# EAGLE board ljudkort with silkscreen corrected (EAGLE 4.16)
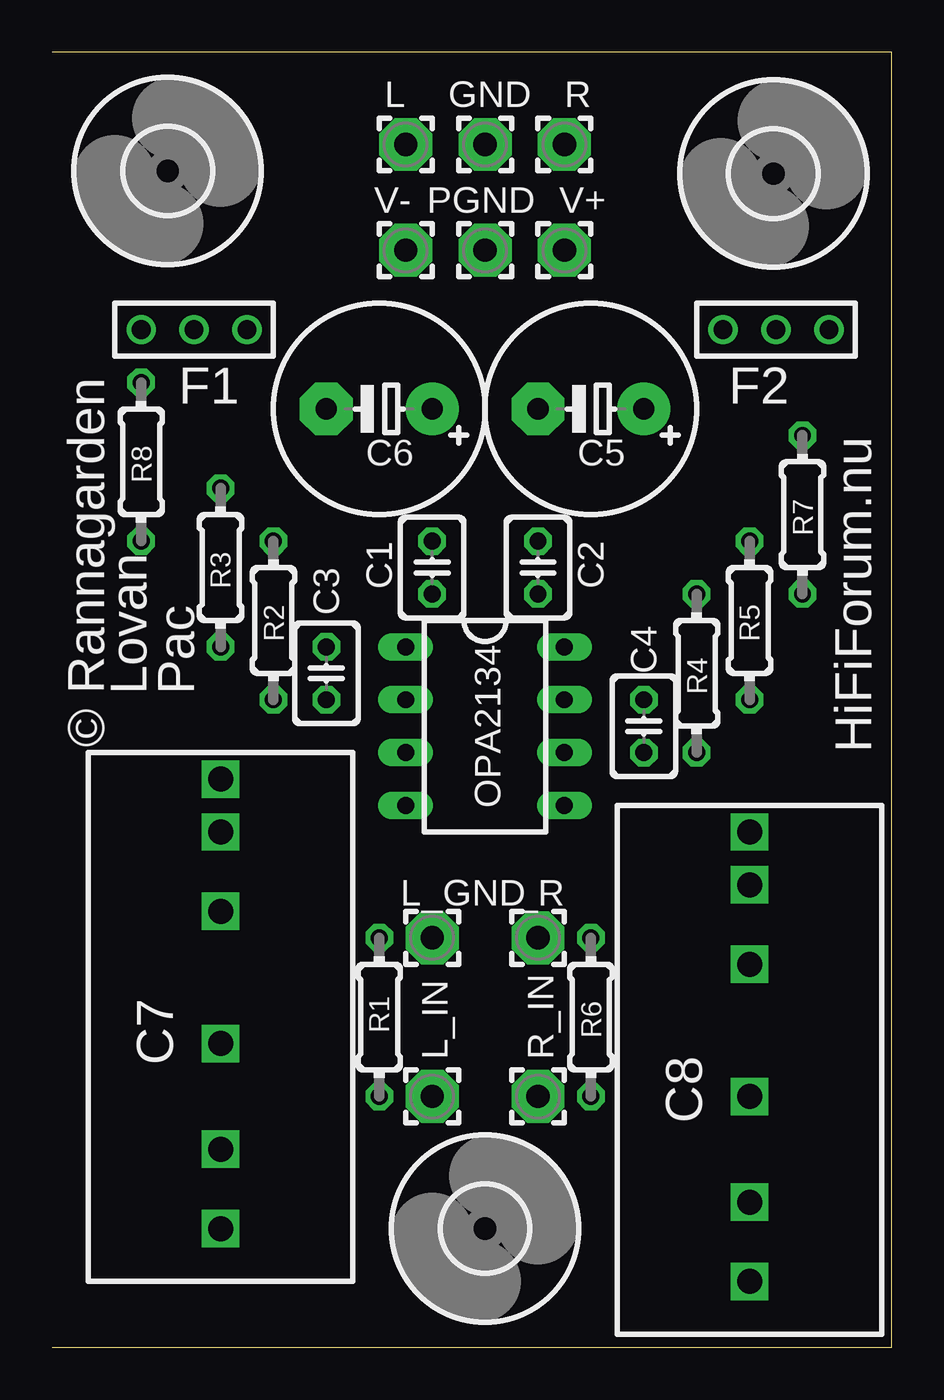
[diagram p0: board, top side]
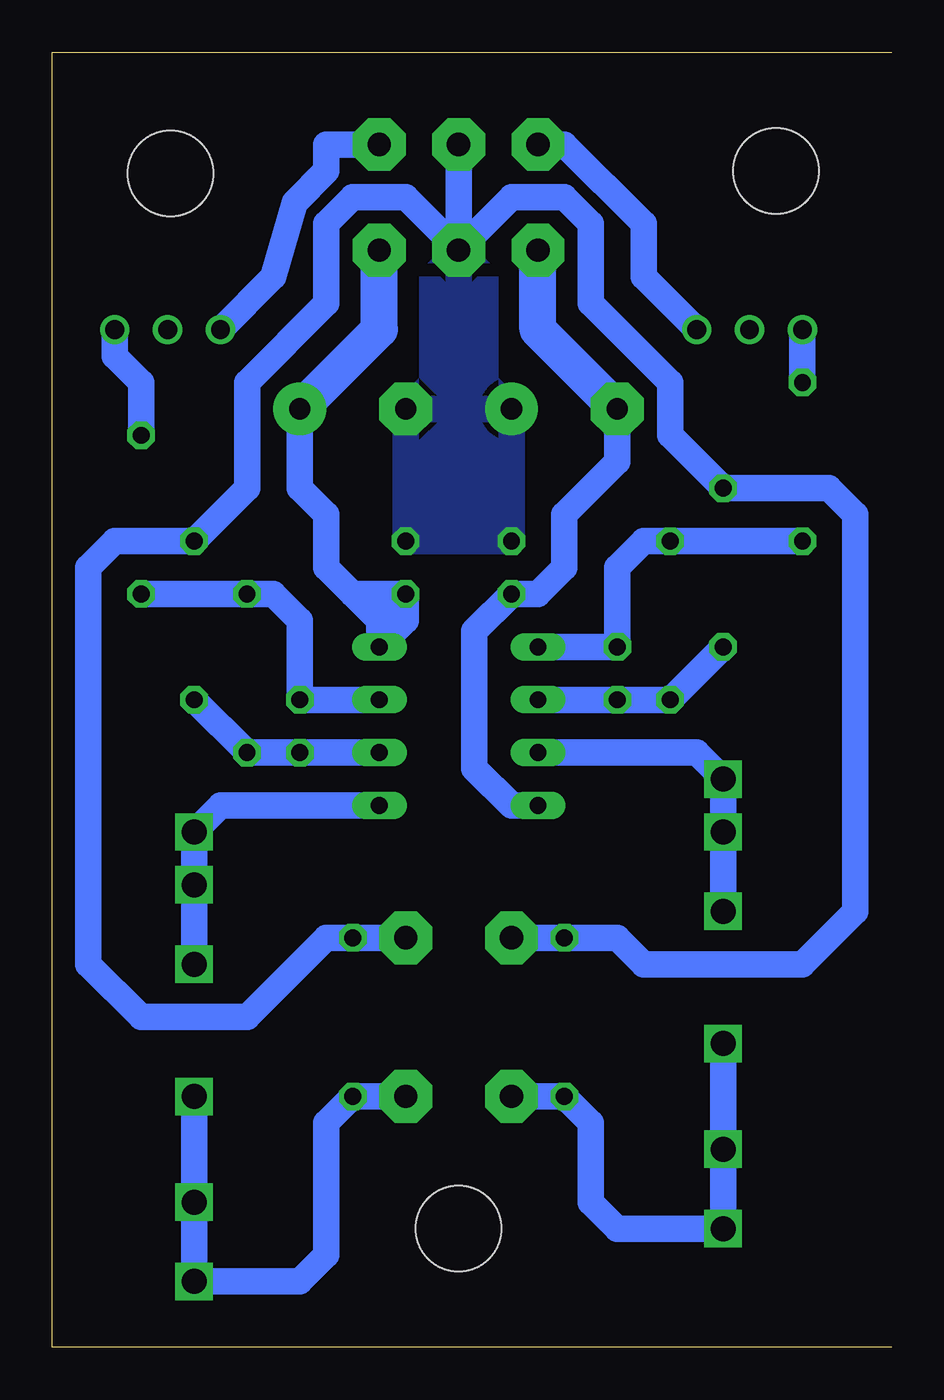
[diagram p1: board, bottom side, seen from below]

Size 40.31 x 62.22 mm. Coordinates in mm from the lower left corner, seen from the top.
Outline: 0,0 40.31,0 40.31,62.22 0,62.22
Copper layers (1*16): Top 0.035mm / dielectric 1.5mm / Bottom 0.035mm
Design rules "10mils": minimum track width 10mil, minimum drill 24mil, track to track 10mil, track to pad 10mil, pad to pad 10mil, via to via 10mil, smd to smd 10mil, copper to edge 40mil, drill to drill 10mil, minimum pad ring 10mil, minimum via ring 8mil, stop-mask expansion 0mil, vias tented up to drill 0mil, thermal gap 10mil

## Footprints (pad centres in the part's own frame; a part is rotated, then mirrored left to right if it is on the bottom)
2,54/1,1 = drill 1.118 pad 2.54 octagon: 1 0,0
C025-030X050 = drill 0.813 octagon: 1 -1.27,0; 2 1.27,0
E5-10,5 = drill 1.016 pad 2.54 round: + -2.54,0 | drill 1.016 pad 2.54 octagon: - 2.54,0
DIL08 = drill 0.813 long: 1 -3.81,-3.81; 2 -1.27,-3.81; 3 1.27,-3.81; 4 3.81,-3.81; 5 3.81,3.81; 6 1.27,3.81; 7 -1.27,3.81; 8 -3.81,3.81
0204/7 = drill 0.813 octagon: 1 -3.81,0; 2 3.81,0
3STIFT = drill 0.9 round: P$1 1.27,1.27; P$2 3.81,1.27; P$3 6.35,1.27
4,1 = hole 4.1: 0,0
KONDING = drill 1.2 square: P$1 0,-11.43; P$2 0,6.35; P$3 0,-8.89; P$4 0,1.27; P$5 0,10.16; P$9 0,-5.08

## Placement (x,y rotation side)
_R  [2,54/1,1]  23.33,19.68 0 top
C1  0,1uf  [C025-030X050]  18.25,37.46 270 top
C2  0,1uf  [C025-030X050]  23.33,37.46 90 top
C3  0,1uf  [C025-030X050]  13.17,32.38 90 top
C4  0,1uf  [C025-030X050]  28.41,29.84 90 top
C5  [E5-10,5]  25.87,45.08 180 top
C6  [E5-10,5]  15.71,45.08 180 top
GND  [2,54/1,1]  20.79,57.78 0 top
L  [2,54/1,1]  16.98,57.78 0 top
L_GND  [2,54/1,1]  18.25,19.68 0 top
L_IN  [2,54/1,1]  18.25,12.06 0 top
OPA2134  OPA2134  [DIL08]  20.79,29.84 270 top
PGND  [2,54/1,1]  20.79,52.7 0 top
R  [2,54/1,1]  24.6,57.78 0 top
R1  200k  [0204/7]  15.71,15.87 90 top
R2  47k  [0204/7]  10.63,34.92 270 top
R3  12k  [0204/7]  8.09,37.46 90 top
R4  47k  [0204/7]  30.95,32.38 270 top
R5  12k  [0204/7]  33.49,34.92 90 top
R6  200k  [0204/7]  25.87,15.87 270 top
R7  0R  [0204/7]  36.03,40 270 top
R8  0R  [0204/7]  4.28,42.54 270 top
R_IN  [2,54/1,1]  23.33,12.06 0 top
U$2  3PINSTIFT  [3STIFT]  3.01,47.62 0 top
U$3  3PINSTIFT  [3STIFT]  38.57,50.16 180 top
U$4  [4,1]  20.79,5.71 0 top
U$5  [4,1]  5.55,56.51 0 top
U$6  [4,1]  34.63,56.38 0 top
U$7  INKONDING  [KONDING]  8.09,15.87 180 top
U$8  INKONDING  [KONDING]  33.49,13.33 180 top
V+  [2,54/1,1]  24.6,52.7 0 top
V-  [2,54/1,1]  16.98,52.7 0 top

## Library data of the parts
_R GND L L_GND L_IN PGND R R_IN V+ V- = wirepad
C1-C6 R1-R8 = rcl
OPA2134 U$2 U$3 U$7 U$8 = Rannagarden
U$4-U$6 = holes

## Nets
GND: _R.1 C1.1 C2.2 C5.- C6.+ GND.1 L_GND.1 PGND.1 R1.2 R3.2 R5.2 R6.1
N$1: L_IN.1 R1.1 U$7.P$2 U$7.P$4 U$7.P$5
N$3: C3.1 OPA2134.2 R2.2 R3.1
N$4: C4.1 OPA2134.6 R4.2 R5.1
N$5: C3.2 OPA2134.1 R2.1 R8.2
N$6: C1.2 C6.- OPA2134.4 V-.1
N$7: C2.1 C5.+ OPA2134.8 V+.1
N$8: C4.2 OPA2134.7 R4.1 R7.2
N$9: R6.2 R_IN.1 U$8.P$2 U$8.P$4 U$8.P$5
N$10: R8.1 U$2.P$1
N$11: R.1 U$3.P$3
N$12: L.1 U$2.P$3
N$13: R7.1 U$3.P$1
N$15: OPA2134.5 U$8.P$1 U$8.P$3 U$8.P$9
N$18: OPA2134.3 U$7.P$1 U$7.P$3 U$7.P$9

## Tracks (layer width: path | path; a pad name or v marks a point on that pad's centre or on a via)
GND
  Bottom 1.27: L_GND.1 R1.2 13.17,19.68 11.9,18.41 4.28,18.41 1.74,20.95 1.74,40 3.01,41.27 R3.2 10.63,43.81 10.63,46.35 14.44,50.16 14.44,53.97 15.71,55.24 18.25,55.24 PGND.1 | R6.1 _R.1 27.14,19.68 30.95,15.87 36.03,15.87 38.57,18.41 38.57,37.46 37.3,38.73 R5.2 30.95,41.27 30.95,46.35 27.14,50.16 27.14,53.97 25.87,55.24 23.33,55.24 PGND.1 | PGND.1 GND.1
  pour Bottom: 20.79,52.7 19.52,51.43 19.52,46.35 18.25,45.08 18.25,38.73 23.33,38.73 23.33,45.08 22.06,46.35 22.06,51.43
N$1
  Bottom 1.27: L_IN.1 R1.1 14.44,10.79 14.44,6.98 13.17,5.71 U$7.P$5 U$7.P$2 U$7.P$4
N$3
  Bottom 1.27: OPA2134.2 C3.1 R2.2 R3.1
N$4
  Bottom 1.27: R5.1 R4.2 C4.1 OPA2134.6
N$5
  Bottom 1.27: OPA2134.1 C3.2 13.17,37.46 11.9,38.73 R2.1 R8.2
N$6
  Bottom 1.27: OPA2134.4 18.25,26.03 20.03,27.81 20.03,34.41 C1.2 16.98,36.19 15.71,37.46 15.71,40 13.17,42.54 C6.-
  Bottom 1.778: C6.- 16.98,48.89 V-.1
N$7
  Bottom 1.27: C5.+ 28.41,41.27 27.14,40 27.14,37.46 25.87,36.19 | 24.6,36.19 C2.1 23.33,34.92 OPA2134.8 | 24.6,36.19 25.87,36.19 | OPA2134.8 24.6,34.92 25.87,36.19 | OPA2134.8 24.6,36.19
  Bottom 1.778: C5.+ 24.6,48.89 V+.1
N$8
  Bottom 1.27: OPA2134.7 C4.2 28.41,34.92 29.68,36.19 R4.1 R7.2
N$9
  Bottom 1.27: R_IN.1 R6.2 27.14,10.79 27.14,4.44 28.41,3.17 U$8.P$5 U$8.P$2 U$8.P$4
N$10
  Bottom 1.27: R8.1 U$2.P$1
N$11
  Bottom 1.27: U$3.P$3 29.68,51.43 28.66,54.99 27.14,56.51 27.14,57.78 R.1
N$12
  Bottom 1.27: U$2.P$3 11.9,51.43 11.9,53.97 15.71,57.78 L.1
N$13
  Bottom 1.27: R7.1 36.03,46.35 37.3,47.62 U$3.P$1
N$15
  Bottom 1.27: U$8.P$9 U$8.P$3 U$8.P$1 32.22,26.03 OPA2134.5
N$18
  Bottom 1.27: U$7.P$9 U$7.P$3 U$7.P$1 9.36,28.57 OPA2134.3

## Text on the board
Bottom: Text
tPlace: Lovan | Pac | © Rannagarden | HiFiForum.nu
tNames: F1 | F2 | C7 | C8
